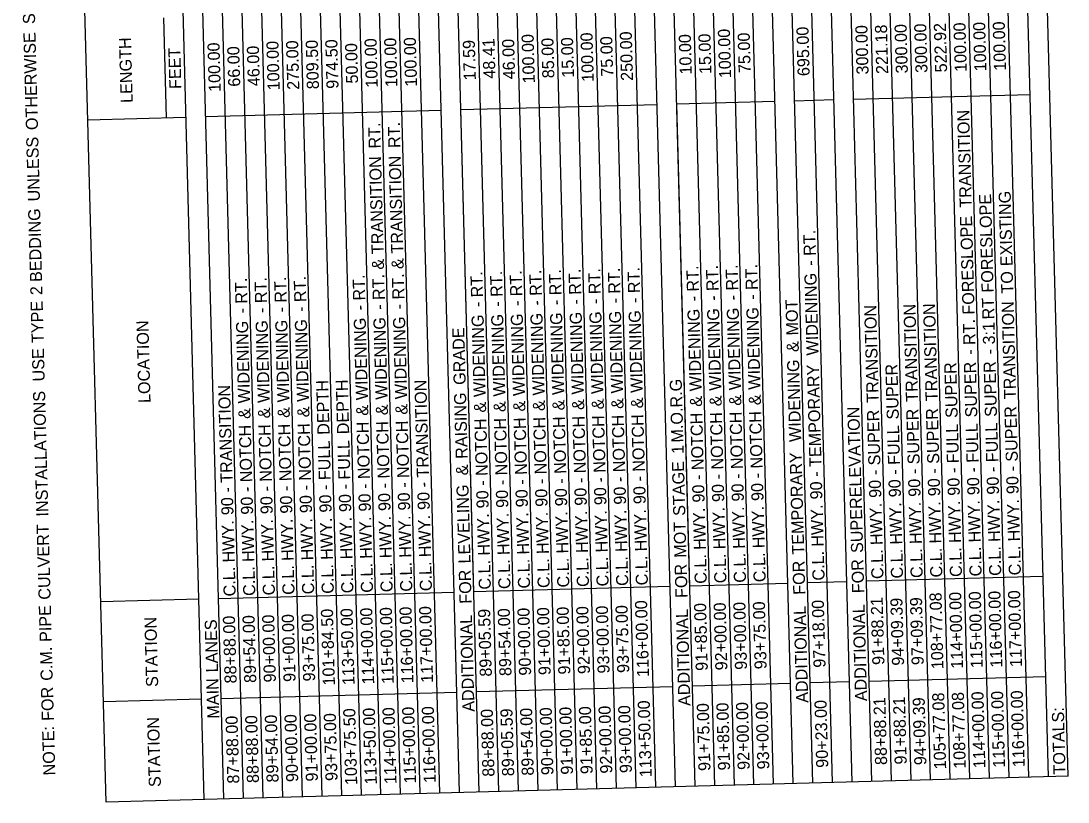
# Model space of a CAD drawing. Extents: x 1930091 to 1931962, y 596452 to 607874.
# Drawn here: x 1930670 to 1931189, y 601439 to 601827 of the extents above; entities that cross this region are included whole.
import ezdxf

# ---------------------------------------------------------------- set-up
doc = ezdxf.new("R2010")
doc.units = 0
doc.layers.add('Default', color=7, linetype='Continuous')

msp = doc.modelspace()

# ---------------------------------------------------------------- linework, layer by layer
at = {"layer": 'Default'}
for p, q in [((1931121.17, 601449.61), (1931080.28, 602972.5)), ((1931130.91, 601449.87), (1931090.03, 602972.76)), ((1931140.66, 601450.14), (1931099.78, 602973.02)), ((1931150.4, 601450.4), (1931109.52, 602973.29)), ((1931160.15, 601450.66), (1931119.27, 602973.55)), ((1931169.9, 601450.92), (1931129.02, 602973.81)), ((1931179.64, 601451.18), (1931138.76, 602974.07)), ((1931189.39, 601451.44), (1931148.51, 602974.33)), ((1930926.24, 601444.38), (1930885.35, 602967.27)), ((1930935.98, 601444.64), (1930895.1, 602967.53)), ((1930945.73, 601444.9), (1930904.85, 602967.79)), ((1930955.48, 601445.16), (1930914.59, 602968.05)), ((1930965.22, 601445.43), (1930924.34, 602968.32)), ((1930974.97, 601445.69), (1930934.09, 602968.58)), ((1930984.71, 601445.95), (1930943.83, 602968.84)), ((1930994.46, 601446.21), (1930953.58, 602969.1)), ((1930994.46, 601446.21), (1930953.58, 602969.1)), ((1931004.21, 601446.47), (1930963.33, 602969.36)), ((1931013.95, 601446.73), (1930973.07, 602969.62)), ((1931023.7, 601447), (1930982.82, 602969.89)), ((1931033.45, 601447.26), (1930992.57, 602970.15)), ((1931043.19, 601447.52), (1931002.31, 602970.41)), ((1931052.94, 601447.78), (1931012.06, 602970.67)), ((1931052.94, 601447.78), (1931012.06, 602970.67)), ((1931062.69, 601448.04), (1931021.81, 602970.93)), ((1931072.43, 601448.3), (1931031.55, 602971.19)), ((1931082.18, 601448.57), (1931041.3, 602971.46)), ((1931082.18, 601448.57), (1931041.3, 602971.46)), ((1931091.93, 601448.83), (1931051.05, 602971.72)), ((1931101.67, 601449.09), (1931060.79, 602971.98)), ((1931111.42, 601449.35), (1931070.54, 602972.24)), ((1930760.55, 601439.93), (1930719.66, 602962.82)), ((1930770.29, 601440.19), (1930729.41, 602963.08)), ((1930780.04, 601440.46), (1930739.16, 602963.34)), ((1930789.78, 601440.72), (1930748.9, 602963.61)), ((1930799.53, 601440.98), (1930758.65, 602963.87)), ((1930809.28, 601441.24), (1930768.4, 602964.13)), ((1930819.02, 601441.5), (1930778.14, 602964.39)), ((1930828.77, 601441.76), (1930787.89, 602964.65)), ((1930838.52, 601442.03), (1930797.64, 602964.91)), ((1930848.26, 601442.29), (1930807.38, 602965.18)), ((1930858.01, 601442.55), (1930817.13, 602965.44)), ((1930867.76, 601442.81), (1930826.88, 602965.7)), ((1930877.5, 601443.07), (1930836.62, 602965.96)), ((1930887.25, 601443.33), (1930846.37, 602966.22)), ((1930887.25, 601443.33), (1930846.37, 602966.22)), ((1930897, 601443.6), (1930856.12, 602966.48)), ((1930906.74, 601443.86), (1930865.86, 602966.75)), ((1930916.49, 601444.12), (1930875.61, 602967.01)), ((1930711.81, 601438.62), (1930670.93, 602961.51)), ((1930741.71, 601778.36), (1930740.37, 601828.07)), ((1931073.09, 601787.26), (1931053.59, 601786.73)), ((1931073.09, 601787.26), (1931053.59, 601786.73)), ((1931170.55, 601789.87), (1931082.83, 601787.52)), ((1931170.55, 601789.87), (1931082.83, 601787.52)), ((1930878.16, 601782.02), (1930761.2, 601778.88)), ((1930878.16, 601782.02), (1930761.2, 601778.88)), ((1930985.37, 601784.9), (1930887.9, 601782.29)), ((1930985.37, 601784.9), (1930887.9, 601782.29)), ((1930894.33, 601543.01), (1930887.9, 601782.29)), ((1931043.85, 601786.47), (1930995.12, 601785.16)), ((1931043.85, 601786.47), (1930995.12, 601785.16)), ((1931001.54, 601545.89), (1930995.12, 601785.16)), ((1930751.45, 601778.62), (1930702.72, 601777.31)), ((1931079.51, 601547.98), (1931060.02, 601547.46)), ((1931079.51, 601547.98), (1931060.02, 601547.46)), ((1931176.98, 601550.6), (1931089.26, 601548.24)), ((1931176.98, 601550.6), (1931089.26, 601548.24)), ((1930884.58, 601542.75), (1930767.62, 601539.61)), ((1930884.58, 601542.75), (1930767.62, 601539.61)), ((1930991.79, 601545.63), (1930894.33, 601543.01)), ((1930991.79, 601545.63), (1930894.33, 601543.01)), ((1931050.27, 601547.2), (1931001.54, 601545.89)), ((1931050.27, 601547.2), (1931001.54, 601545.89)), ((1930757.88, 601539.35), (1930709.14, 601538.04)), ((1930993.13, 601495.92), (1930895.66, 601493.3)), ((1930993.13, 601495.92), (1930895.66, 601493.3)), ((1931051.61, 601497.49), (1931002.87, 601496.18)), ((1931051.61, 601497.49), (1931002.87, 601496.18)), ((1931080.85, 601498.27), (1931061.35, 601497.75)), ((1931080.85, 601498.27), (1931061.35, 601497.75)), ((1931178.31, 601500.89), (1931090.59, 601498.53)), ((1931178.31, 601500.89), (1931090.59, 601498.53)), ((1930885.92, 601493.04), (1930768.96, 601489.9)), ((1930885.92, 601493.04), (1930768.96, 601489.9)), ((1930759.21, 601489.64), (1930710.48, 601488.33)), ((1931189.39, 601451.44), (1930711.81, 601438.62)), ((1931189.39, 601451.44), (1930711.81, 601438.62))]:
    msp.add_line(p, q, dxfattribs=at)

# ---------------------------------------------------------------- texts
for s, p in [(' SPECIFIED.', (1930676.64, 601822.79)), ('300.00', (1931090.38, 601799.97)), ('221.18', (1931100.12, 601800.22)), ('300.00', (1931109.87, 601800.5)), ('300.00', (1931119.62, 601800.76)), ('522.92', (1931129.36, 601801.04)), ('100.00', (1931139.11, 601801.28)), ('100.00', (1931148.86, 601801.54)), ('100.00', (1931158.6, 601801.81)), (' OTHERWISE', (1930678.06, 601770.16)), ('100.00', (1930924.69, 601795.53)), ('100.00', (1930953.93, 601796.31)), ('75.00', (1930963.61, 601798.9)), ('250.00', (1930973.42, 601796.84)), ('10.00', (1931002.6, 601799.95)), ('15.00', (1931012.34, 601800.21)), ('100.00', (1931022.15, 601798.14)), ('75.00', (1931031.84, 601800.73)), ('695.00', (1931061.14, 601799.19)), ('LENGTH', (1930725, 601785.87)), ('100.00', (1930768.74, 601791.34)), ('66.00', (1930778.43, 601793.93)), ('46.00', (1930788.17, 601794.19)), ('100.00', (1930797.98, 601792.13)), ('275.00', (1930807.73, 601792.39)), ('809.50', (1930817.48, 601792.65)), ('974.50', (1930827.22, 601792.91)), ('50.00', (1930836.91, 601795.5)), ('100.00', (1930846.72, 601793.43)), ('100.00', (1930856.46, 601793.7)), ('100.00', (1930866.21, 601793.96)), ('17.59', (1930895.39, 601797.06)), ('48.41', (1930905.12, 601797.9)), ('46.00', (1930914.88, 601797.59)), ('85.00', (1930934.37, 601798.12)), ('15.00', (1930944.12, 601798.38)), ('FEET', (1930749.2, 601792.8)), (' TRANSITION', (1931141.65, 601731.63)), (' RT.', (1930848.26, 601760.99)), (' RT.', (1930858.01, 601761.25)), (' UNLESS', (1930679.01, 601734.73)), (' TRANSITION', (1930849.67, 601708.59)), (' TRANSITION', (1930859.41, 601708.85)), (' FORESLOPE', (1931152.54, 601689.45)), (' EXISTING', (1931161.94, 601702.56)), (' BEDDING', (1930680.08, 601694.75)), (' FORESLOPE', (1931143.08, 601678.52)), (' RT.', (1931064.27, 601707.7)), (' &', (1930849.88, 601700.87)), (' &', (1930859.62, 601701.13)), (' RT.', (1931006.22, 601689.96)), (' RT.', (1931015.97, 601690.22)), (' RT.', (1931025.72, 601690.48)), (' RT.', (1931035.46, 601690.74)), (' -', (1931064.4, 601702.85)), (' RT.', (1930801.55, 601684.46)), (' RT.', (1930811.29, 601684.72)), (' RT.', (1930840.53, 601685.51)), (' RT.', (1930850.28, 601685.77)), (' RT.', (1930860.03, 601686.03)), (' RT.', (1930899.01, 601687.08)), (' RT.', (1930908.76, 601687.34)), (' RT.', (1930918.51, 601687.6)), (' RT.', (1930928.25, 601687.86)), (' RT.', (1930938, 601688.12)), (' RT.', (1930947.75, 601688.39)), (' RT.', (1930957.49, 601688.65)), (' RT.', (1930967.24, 601688.91)), (' RT.', (1930976.99, 601689.17)), (' WIDENING', (1931065.6, 601658.22)), (' TO', (1931162.31, 601688.97)), (' 2', (1930680.26, 601688.2)), (' RT.', (1930782.06, 601683.94)), (' RT.', (1930791.8, 601684.2)), (' -', (1930957.62, 601683.79)), (' -', (1930967.37, 601684.05)), (' -', (1930977.12, 601684.32)), (' -', (1931006.35, 601685.1)), (' -', (1931016.1, 601685.36)), (' -', (1931025.85, 601685.62)), (' -', (1931035.59, 601685.89)), (' RT', (1931152.9, 601676.12)), (' TYPE', (1930680.9, 601664.43)), (' -', (1930782.19, 601679.08)), (' -', (1930791.93, 601679.35)), (' -', (1930801.68, 601679.61)), (' -', (1930811.43, 601679.87)), (' -', (1930840.66, 601680.65)), (' -', (1930850.41, 601680.91)), (' -', (1930860.16, 601681.18)), (' -', (1930899.14, 601682.22)), (' -', (1930908.89, 601682.48)), (' -', (1930918.64, 601682.75)), (' -', (1930928.38, 601683.01)), (' -', (1930938.13, 601683.27)), (' -', (1930947.88, 601683.53)), (' WIDENING', (1931007.55, 601640.47)), (' WIDENING', (1931017.3, 601640.73)), (' WIDENING', (1931027.05, 601640.99)), (' WIDENING', (1931036.79, 601641.25)), (' MOT', (1931055.58, 601668.16)), (' TRANSITION', (1931095.49, 601634.74)), (' TRANSITION', (1931114.98, 601635.26)), (' TRANSITION', (1931124.73, 601635.53)), (' TRANSITION', (1931163.71, 601636.57)), (' WIDENING', (1930841.86, 601636.02)), (' WIDENING', (1930851.61, 601636.28)), (' WIDENING', (1930861.36, 601636.54)), (' WIDENING', (1930900.34, 601637.59)), (' WIDENING', (1930910.09, 601637.85)), (' WIDENING', (1930919.83, 601638.11)), (' WIDENING', (1930929.58, 601638.38)), (' WIDENING', (1930939.33, 601638.64)), (' WIDENING', (1930949.07, 601638.9)), (' WIDENING', (1930958.82, 601639.16)), (' WIDENING', (1930968.57, 601639.42)), (' WIDENING', (1930978.31, 601639.68)), ('LOCATION', (1930733.88, 601636.87)), (' WIDENING', (1930783.38, 601634.45)), (' WIDENING', (1930793.13, 601634.71)), (' WIDENING', (1930802.88, 601634.98)), (' WIDENING', (1930812.62, 601635.24)), (' GRADE', (1930890.43, 601643.64)), (' RT.', (1931143.49, 601663.42)), (' 3:1', (1931153.23, 601663.69)), (' USE', (1930681.41, 601645.32)), (' &', (1931055.8, 601659.92)), (' -', (1931143.62, 601658.57)), (' -', (1931153.36, 601658.83)), (' WIDENING', (1931057, 601615.27)), (' SUPER', (1931154.2, 601627.74)), (' TEMPORARY', (1931067.08, 601602.87)), (' SUPER', (1931105.46, 601626.43)), (' SUPER', (1931134.7, 601627.22)), (' SUPER', (1931144.45, 601627.48)), (' DEPTH', (1930822.82, 601618.84)), (' DEPTH', (1930832.56, 601619.11)), (' TRANSITION', (1930872.15, 601597.63)), (' M.O.R.G', (1930998.48, 601614.99)), (' INSTALLATIONS', (1930683.21, 601578.23)), (' TRANSITION', (1930774.69, 601595.02)), (' RAISING', (1930891.41, 601606.9)), (' &', (1930861.56, 601628.82)), (' &', (1930900.55, 601629.87)), (' &', (1930910.3, 601630.13)), (' &', (1930920.04, 601630.39)), (' &', (1930929.79, 601630.65)), (' &', (1930939.53, 601630.91)), (' &', (1930949.28, 601631.17)), (' &', (1930959.03, 601631.44)), (' &', (1930968.77, 601631.7)), (' &', (1930978.52, 601631.96)), (' &', (1931007.76, 601632.74)), (' &', (1931017.51, 601633.01)), (' &', (1931027.25, 601633.27)), (' &', (1931037, 601633.53)), (' &', (1930783.59, 601626.73)), (' &', (1930793.34, 601626.99)), (' &', (1930803.08, 601627.25)), (' &', (1930812.83, 601627.51)), (' &', (1930842.07, 601628.3)), (' &', (1930851.82, 601628.56)), (' NOTCH', (1931008.6, 601601.3)), (' NOTCH', (1931018.35, 601601.56)), (' NOTCH', (1931028.1, 601601.82)), (' NOTCH', (1931037.84, 601602.08)), (' SUPERELEVATION', (1931087.74, 601560.16)), (' SUPER', (1931096.32, 601603.65)), (' SUPER', (1931115.82, 601604.17)), (' SUPER', (1931125.56, 601604.44)), (' SUPER', (1931164.55, 601605.48)), (' NOTCH', (1930803.93, 601595.8)), (' NOTCH', (1930813.67, 601596.06)), (' NOTCH', (1930842.91, 601596.85)), (' NOTCH', (1930852.66, 601597.11)), (' NOTCH', (1930862.41, 601597.37)), (' NOTCH', (1930901.39, 601598.42)), (' NOTCH', (1930911.14, 601598.68)), (' NOTCH', (1930920.89, 601598.94)), (' NOTCH', (1930930.63, 601599.2)), (' NOTCH', (1930940.38, 601599.46)), (' NOTCH', (1930950.13, 601599.73)), (' NOTCH', (1930959.87, 601599.99)), (' NOTCH', (1930969.62, 601600.25)), (' NOTCH', (1930979.37, 601600.51)), (' FULL', (1931135.31, 601604.7)), (' FULL', (1931145.06, 601604.96)), (' FULL', (1931154.8, 601605.22)), (' NOTCH', (1930784.44, 601595.28)), (' NOTCH', (1930794.18, 601595.54)), (' FULL', (1931106.07, 601603.91)), (' FULL', (1930823.42, 601596.32)), (' FULL', (1930833.17, 601596.59)), (' 1', (1930998.63, 601609.36)), (' TEMPORARY', (1931058.5, 601559.37)), (' &', (1930891.63, 601598.66)), (' STAGE', (1930999.46, 601578.58)), (' -', (1931164.68, 601600.63)), (' -', (1930969.75, 601595.39)), (' -', (1930979.5, 601595.66)), (' -', (1931008.73, 601596.44)), (' -', (1931018.48, 601596.7)), (' -', (1931028.23, 601596.96)), (' -', (1931037.97, 601597.23)), (' -', (1931067.21, 601598.01)), (' -', (1931096.45, 601598.8)), (' -', (1931106.2, 601599.06)), (' -', (1931115.95, 601599.32)), (' -', (1931125.69, 601599.58)), (' -', (1931135.44, 601599.84)), (' -', (1931145.19, 601600.1)), (' 90', (1931155.23, 601589.12)), (' -', (1931154.93, 601600.37)), (' 90', (1931164.98, 601589.39)), (' -', (1930784.57, 601590.42)), (' -', (1930794.31, 601590.69)), (' -', (1930804.06, 601590.95)), (' -', (1930813.81, 601591.21)), (' -', (1930823.55, 601591.47)), (' -', (1930833.3, 601591.73)), (' -', (1930843.04, 601591.99)), (' -', (1930852.79, 601592.25)), (' -', (1930862.54, 601592.52)), (' -', (1930872.28, 601592.78)), (' LEVELING', (1930892.81, 601554.93)), (' -', (1930901.52, 601593.56)), (' -', (1930911.27, 601593.82)), (' -', (1930921.02, 601594.09)), (' -', (1930930.76, 601594.35)), (' -', (1930940.51, 601594.61)), (' -', (1930950.26, 601594.87)), (' 90', (1930960.3, 601583.89)), (' -', (1930960, 601595.13)), (' 90', (1930970.05, 601584.15)), (' 90', (1930979.8, 601584.41)), (' 90', (1931009.04, 601585.2)), (' 90', (1931018.78, 601585.46)), (' 90', (1931028.53, 601585.72)), (' 90', (1931038.28, 601585.98)), (' 90', (1931067.52, 601586.77)), (' 90', (1931096.75, 601587.55)), (' 90', (1931106.5, 601587.82)), (' 90', (1931116.25, 601588.08)), (' 90', (1931125.99, 601588.34)), (' 90', (1931135.74, 601588.6)), (' 90', (1931145.49, 601588.86)), (' 90', (1930775.12, 601578.92)), (' -', (1930774.82, 601590.16)), (' 90', (1930784.87, 601579.18)), (' 90', (1930794.61, 601579.44)), (' 90', (1930804.36, 601579.71)), (' 90', (1930814.11, 601579.97)), (' 90', (1930823.85, 601580.23)), (' 90', (1930833.6, 601580.49)), (' 90', (1930843.35, 601580.75)), (' 90', (1930853.09, 601581.01)), (' 90', (1930862.84, 601581.28)), (' 90', (1930872.59, 601581.54)), (' 90', (1930901.83, 601582.32)), (' 90', (1930911.57, 601582.58)), (' 90', (1930921.32, 601582.84)), (' 90', (1930931.06, 601583.11)), (' 90', (1930940.81, 601583.37)), (' 90', (1930950.56, 601583.63)), (' HWY.', (1931019.41, 601561.99)), (' HWY.', (1931029.16, 601562.25)), (' HWY.', (1931038.91, 601562.51)), (' HWY.', (1931068.15, 601563.29)), (' HWY.', (1931097.39, 601564.08)), (' HWY.', (1931107.13, 601564.34)), (' HWY.', (1931116.88, 601564.6)), (' HWY.', (1931126.62, 601564.86)), (' HWY.', (1931136.37, 601565.13)), (' HWY.', (1931146.12, 601565.39)), (' HWY.', (1931155.86, 601565.65)), (' HWY.', (1931165.61, 601565.91)), (' HWY.', (1930824.48, 601556.75)), (' HWY.', (1930834.23, 601557.02)), (' HWY.', (1930843.98, 601557.28)), (' HWY.', (1930853.72, 601557.54)), (' HWY.', (1930863.47, 601557.8)), (' HWY.', (1930873.22, 601558.06)), (' HWY.', (1930902.46, 601558.85)), (' HWY.', (1930912.2, 601559.11)), (' HWY.', (1930921.95, 601559.37)), (' HWY.', (1930931.69, 601559.63)), (' HWY.', (1930941.44, 601559.89)), (' HWY.', (1930951.19, 601560.16)), (' HWY.', (1930960.93, 601560.42)), (' HWY.', (1930970.68, 601560.68)), (' HWY.', (1930980.43, 601560.94)), (' HWY.', (1931009.67, 601561.72)), (' CULVERT', (1930684.32, 601536.96)), (' HWY.', (1930775.75, 601555.45)), (' HWY.', (1930785.5, 601555.71)), (' HWY.', (1930795.24, 601555.97)), (' HWY.', (1930804.99, 601556.23)), (' HWY.', (1930814.74, 601556.49)), (' MOT', (1931000.02, 601557.8)), ('C.L.', (1931107.52, 601549.71)), ('C.L.', (1931117.27, 601549.97)), ('C.L.', (1931127.02, 601550.23)), ('C.L.', (1931136.76, 601550.49)), ('C.L.', (1931146.51, 601550.75)), ('C.L.', (1931156.26, 601551.02)), ('C.L.', (1931166, 601551.28)), ('C.L.', (1930912.59, 601544.48)), ('C.L.', (1930922.34, 601544.74)), ('C.L.', (1930932.09, 601545)), ('C.L.', (1930941.83, 601545.26)), ('C.L.', (1930951.58, 601545.52)), ('C.L.', (1930961.33, 601545.78)), ('C.L.', (1930971.07, 601546.04)), ('C.L.', (1930980.82, 601546.31)), ('C.L.', (1931010.06, 601547.09)), ('C.L.', (1931019.81, 601547.35)), ('C.L.', (1931029.55, 601547.61)), ('C.L.', (1931039.3, 601547.88)), ('C.L.', (1931068.54, 601548.66)), (' FOR', (1931088.27, 601540.18)), ('C.L.', (1931097.78, 601549.45)), ('C.L.', (1930776.14, 601540.81)), ('C.L.', (1930785.89, 601541.07)), ('C.L.', (1930795.64, 601541.34)), ('C.L.', (1930805.38, 601541.6)), ('C.L.', (1930815.13, 601541.86)), ('C.L.', (1930824.88, 601542.12)), ('C.L.', (1930834.62, 601542.38)), ('C.L.', (1930844.37, 601542.64)), ('C.L.', (1930854.12, 601542.91)), ('C.L.', (1930863.86, 601543.17)), ('C.L.', (1930873.61, 601543.43)), (' FOR', (1930893.34, 601534.95)), ('C.L.', (1930902.85, 601544.21)), (' FOR', (1931000.55, 601537.83)), (' FOR', (1931059.03, 601539.4)), ('114+00.00', (1931137.31, 601504.93)), ('115+00.00', (1931147.06, 601505.2)), ('116+00.00', (1931156.8, 601505.46)), ('117+00.00', (1931166.55, 601505.72)), ('116+00.00', (1930981.37, 601500.75)), ('93+00.00', (1931030.04, 601504.39)), ('93+75.00', (1931039.78, 601504.65)), ('97+18.00', (1931069.02, 601505.43)), ('91+88.21', (1931098.25, 601506.79)), ('94+09.39', (1931108.01, 601506.46)), ('97+09.39', (1931117.76, 601506.72)), ('108+77.08', (1931127.57, 601504.66)), (' PIPE', (1930684.88, 601515.98)), ('101+84.50', (1930825.42, 601496.56)), ('113+50.00', (1930835.17, 601496.82)), ('114+00.00', (1930844.92, 601497.08)), ('115+00.00', (1930854.66, 601497.35)), ('116+00.00', (1930864.41, 601497.61)), ('117+00.00', (1930874.16, 601497.87)), ('89+05.59', (1930903.33, 601500.97)), ('89+54.00', (1930913.08, 601501.25)), ('90+00.00', (1930922.83, 601501.51)), ('91+00.00', (1930932.57, 601501.77)), ('91+85.00', (1930942.32, 601502.03)), ('92+00.00', (1930952.07, 601502.29)), ('93+00.00', (1930961.81, 601502.55)), ('93+75.00', (1930971.56, 601502.82)), ('ADDITIONAL', (1931001.94, 601486.4)), ('91+85.00', (1931010.54, 601503.86)), ('92+00.00', (1931020.29, 601504.12)), ('ADDITIONAL', (1931060.41, 601487.97)), ('ADDITIONAL', (1931089.65, 601488.76)), ('STATION', (1930737.66, 601495.86)), (' LANES', (1930767.46, 601500.86)), ('88+88.00', (1930776.63, 601497.58)), ('89+54.00', (1930786.38, 601497.84)), ('90+00.00', (1930796.12, 601498.11)), ('91+00.00', (1930805.87, 601498.37)), ('93+75.00', (1930815.61, 601498.63)), ('ADDITIONAL', (1930894.72, 601483.52)), (' C.M.', (1930685.4, 601496.69)), ('MAIN', (1930768.02, 601480.12)), (' FOR', (1930685.93, 601476.79)), ('105+77.08', (1931128.9, 601454.95)), ('108+77.08', (1931138.65, 601455.21)), ('114+00.00', (1931148.39, 601455.49)), ('115+00.00', (1931158.14, 601455.75)), ('116+00.00', (1931167.89, 601456.01)), ('115+00.00', (1930865.74, 601447.9)), ('116+00.00', (1930875.49, 601448.16)), ('91+00.00', (1930943.65, 601452.32)), ('91+85.00', (1930953.4, 601452.59)), ('92+00.00', (1930963.15, 601452.85)), ('93+00.00', (1930972.89, 601453.11)), ('113+50.00', (1930982.7, 601451.04)), ('91+75.00', (1931011.88, 601454.15)), ('91+85.00', (1931021.63, 601454.42)), ('92+00.00', (1931031.37, 601454.68)), ('93+00.00', (1931041.12, 601454.94)), ('90+23.00', (1931070.36, 601455.72)), ('88+88.21', (1931099.58, 601457.08)), ('91+88.21', (1931109.33, 601457.34)), ('94+09.39', (1931119.09, 601457.02)), ('87+88.00', (1930777.96, 601447.88)), ('88+88.00', (1930787.71, 601448.14)), ('89+54.00', (1930797.46, 601448.4)), ('90+00.00', (1930807.2, 601448.66)), ('91+00.00', (1930816.95, 601448.92)), ('93+75.00', (1930826.7, 601449.18)), ('103+75.50', (1930836.5, 601447.12)), ('113+50.00', (1930846.25, 601447.38)), ('114+00.00', (1930856, 601447.64)), ('88+88.00', (1930904.67, 601451.28)), ('89+05.59', (1930914.41, 601451.52)), ('89+54.00', (1930924.16, 601451.8)), ('90+00.00', (1930933.91, 601452.06)), ('TOTALS:', (1931188.17, 601452.39)), ('NOTE:', (1930686.6, 601451.91)), ('STATION', (1930739, 601446.16))]:
    msp.add_text(s, height=6, rotation=91.5377, dxfattribs=at).set_placement(p)

doc.saveas('drawing.dxf')
